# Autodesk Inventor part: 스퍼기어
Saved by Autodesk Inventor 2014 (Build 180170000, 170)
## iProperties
Created: 2026-09
Part Number: 스퍼기어
Material: 강철, 합금
Document SubType Name: Modeling
Designer: dg
Density: 7.85 g/cm^3
Appearance: 반연마
Mass: 168.588 g
Surface Area: 63.3613 cm^2
Volume: 21.4762 cm^3
Author: jhkim
Creation Date: 2026-08-26
Sending System: Autodesk Inventor 2027
Preprocessor: ST-DEVELOPER v20.1
Author: dg
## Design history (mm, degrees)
node "스퍼기어1"
node "솔리드1"
node "기준1"
